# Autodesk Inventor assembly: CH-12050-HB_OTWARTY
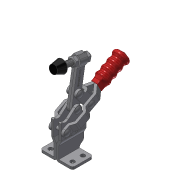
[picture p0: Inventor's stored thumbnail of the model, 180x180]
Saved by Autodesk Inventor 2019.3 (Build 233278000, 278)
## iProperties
Company: Î¢ÈíÖÐ¹ú
Created: 2012-07
Part Number: CH-12050-HB_OTWARTY
Material: Ogólny
Description: STEP AP203
Document SubType Name: Assembly
Designer: CADENGINEERING4
Sending System: SolidWorks 2010
Preprocessor: SwSTEP 2.0
Title: CH-12050-HB.STEP
Author: Î¢ÈíÓÃ»§
Revision Number: ÈÎºÎ
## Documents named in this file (10)
- D:\Vault_2016\Projekty\NASZ KATALOG\CLAMPTEK\STRONA\Vertical toggle clamp\CH-12050-HB\CH-12050-HB_OTWARTY.iam
- D:\Vault_2016\Projekty\NASZ KATALOG\CLAMPTEK\STEP FILES\Vertical toggle clamp\CH-12050-HB\CH-12050-07.ipt
- D:\Vault_2016\Projekty\NASZ KATALOG\CLAMPTEK\STEP FILES\Vertical toggle clamp\CH-12050-HB\CH-FC-14134 Nut.ipt
- D:\Vault_2016\Projekty\NASZ KATALOG\CLAMPTEK\STEP FILES\Vertical toggle clamp\CH-12050-HB\CH-12050-06.ipt
- D:\Vault_2016\Projekty\NASZ KATALOG\CLAMPTEK\STEP FILES\Vertical toggle clamp\CH-12050-HB\CH-12050-HB-02 FIXED SPINDLE.ipt
- D:\Vault_2016\Projekty\NASZ KATALOG\CLAMPTEK\STEP FILES\Vertical toggle clamp\CH-12050-HB\CH-12050-HB-01 FLANGED BASE.ipt
- D:\Vault_2016\Projekty\NASZ KATALOG\CLAMPTEK\STEP FILES\Vertical toggle clamp\CH-12050-HB\CH-FC-14134 SPINDLE SUPPLIED.ipt
- D:\Vault_2016\Projekty\NASZ KATALOG\CLAMPTEK\STEP FILES\Vertical toggle clamp\CH-12050-HB\CH-12050-04 CONNECTING-PLATE.ipt
- D:\Vault_2016\Projekty\NASZ KATALOG\CLAMPTEK\STEP FILES\Vertical toggle clamp\CH-12050-HB\CH-12050-03 STRAIGHT HANDLE.ipt
- D:\Vault_2016\Projekty\NASZ KATALOG\CLAMPTEK\STEP FILES\Vertical toggle clamp\CH-12050-HB\CH-12050-05.ipt
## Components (12 placed, 9 different names)
1. CH-12050-HB-01 FLANGED BASE_7
2. CH-12050-07:3 — Zestawiające:4, Zestawiające:5
3. CH-FC-14134 Nut:3 — Zestawiające:18, Zestawiające:20
4. CH-12050-06:3 — Zestawiające:1, Zestawiające:2, Zestawiające:3
5. CH-FC-14134 Nut:4 — Zestawiające:19, Zestawiające:21, Zestawiające:22
6. CH-12050-07:4 — Zestawiające:6, Zestawiające:7, Zestawiające:25
7. CH-12050-HB-02 FIXED SPINDLE:2 — Zestawiające:4, Zestawiające:7, Zestawiające:8, Równoległe:1, Zestawiające:20, Zestawiające:21, Zestawiające:22
8. CH-FC-14134 SPINDLE SUPPLIED:2 — Zestawiające:18, Zestawiające:19, Równoległe:1
9. CH-12050-04 CONNECTING-PLATE:2 — Zestawiające:5, Zestawiające:6, Zestawiające:8, Zestawiające:9, Zestawiające:10, Zestawiające:11, Zestawiające:25
10. CH-12050-06:4 — Zestawiające:10, Zestawiające:11, Zestawiające:12, Zestawiające:13, Zestawiające:14
11. CH-12050-03 STRAIGHT HANDLE:2 — Zestawiające:1, Zestawiające:2, Zestawiające:3, Zestawiające:9, Zestawiające:12, Zestawiające:13, Zestawiające:14, Zestawiające:15, Zestawiające:16, Zestawiające:17
12. CH-12050-05:2 — Zestawiające:15, Zestawiające:16, Zestawiające:17
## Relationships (24: Mate 23, Flush 1)
- Zestawiające:1 [Mate]: CH-12050-06:3 ↔ CH-12050-03 STRAIGHT HANDLE:2
- Zestawiające:2 [Mate]: CH-12050-06:3 ↔ CH-12050-03 STRAIGHT HANDLE:2
- Zestawiające:3 [Mate]: CH-12050-06:3 ↔ CH-12050-03 STRAIGHT HANDLE:2
- Zestawiające:4 [Mate]: CH-12050-07:3 ↔ CH-12050-HB-02 FIXED SPINDLE:2
- Zestawiające:5 [Mate]: CH-12050-07:3 ↔ CH-12050-04 CONNECTING-PLATE:2
- Zestawiające:6 [Mate]: CH-12050-07:4 ↔ CH-12050-04 CONNECTING-PLATE:2
- Zestawiające:7 [Mate]: CH-12050-07:4 ↔ CH-12050-HB-02 FIXED SPINDLE:2
- Zestawiające:8 [Mate]: CH-12050-HB-02 FIXED SPINDLE:2 ↔ CH-12050-04 CONNECTING-PLATE:2
- Zestawiające:9 [Mate]: CH-12050-04 CONNECTING-PLATE:2 ↔ CH-12050-03 STRAIGHT HANDLE:2
- Zestawiające:10 [Mate]: CH-12050-04 CONNECTING-PLATE:2 ↔ CH-12050-06:4
- Zestawiające:11 [Mate]: CH-12050-04 CONNECTING-PLATE:2 ↔ CH-12050-06:4
- Zestawiające:12 [Mate]: CH-12050-06:4 ↔ CH-12050-03 STRAIGHT HANDLE:2
- Zestawiające:13 [Mate]: CH-12050-06:4 ↔ CH-12050-03 STRAIGHT HANDLE:2
- Zestawiające:14 [Mate]: CH-12050-06:4 ↔ CH-12050-03 STRAIGHT HANDLE:2
- Zestawiające:15 [Mate]: CH-12050-03 STRAIGHT HANDLE:2 ↔ CH-12050-05:2
- Zestawiające:16 [Mate]: CH-12050-03 STRAIGHT HANDLE:2 ↔ CH-12050-05:2
- Zestawiające:17 [Mate]: CH-12050-03 STRAIGHT HANDLE:2 ↔ CH-12050-05:2
- Zestawiające:18 [Mate]: CH-FC-14134 Nut:3 ↔ CH-FC-14134 SPINDLE SUPPLIED:2
- Zestawiające:19 [Mate]: CH-FC-14134 Nut:4 ↔ CH-FC-14134 SPINDLE SUPPLIED:2
- Równoległe:1 [Flush]: CH-12050-HB-02 FIXED SPINDLE:2 ↔ CH-FC-14134 SPINDLE SUPPLIED:2
- Zestawiające:20 [Mate]: CH-FC-14134 Nut:3 ↔ CH-12050-HB-02 FIXED SPINDLE:2
- Zestawiające:21 [Mate]: CH-FC-14134 Nut:4 ↔ CH-12050-HB-02 FIXED SPINDLE:2
- Zestawiające:22 [Mate]: CH-FC-14134 Nut:4 ↔ CH-12050-HB-02 FIXED SPINDLE:2
- Zestawiające:25 [Mate]: CH-12050-07:4 ↔ CH-12050-04 CONNECTING-PLATE:2
